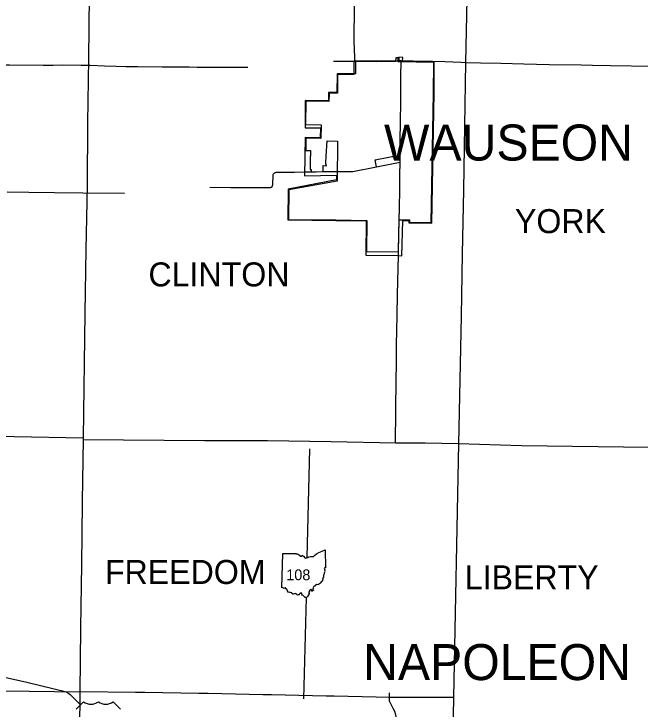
# Model space of a CAD drawing. Extents: x -232 to 448, y 619 to 1059.
# Drawn here: x -26 to 27.5, y 848 to 907.4 of the extents above; entities that cross this region are included whole.
import ezdxf

# ---------------------------------------------------------------- set-up
doc = ezdxf.new("R2010")
doc.units = 0
doc.layers.add('Default', color=7, linetype='Continuous')

msp = doc.modelspace()

# ---------------------------------------------------------------- linework, layer by layer
at = {"layer": 'Default'}
for p, q in [((6.915, 903.671), (6.906, 903.352)), ((7.234, 903.661), (6.915, 903.671)), ((7.225, 903.354), (7.234, 903.661)), ((9.867, 900.61), (9.88, 903.222)), ((9.918, 900.609), (9.932, 903.272)), ((3.195, 902.256), (1.628, 902.256)), ((3.064, 902.205), (1.678, 902.205)), ((0.892, 900.667), (0.884, 899.949)), ((1.61, 900.659), (0.892, 900.667)), ((0.942, 900.615), (0.934, 899.897)), ((1.661, 900.607), (0.942, 900.615)), ((-1.082, 899.971), (-1.108, 897.642)), ((0.884, 899.949), (-1.082, 899.971)), ((-1.031, 899.919), (-1.054, 897.926)), ((0.934, 899.897), (-1.031, 899.919)), ((-1.054, 897.926), (0.259, 897.912)), ((0.203, 897.634), (0.189, 896.784)), ((0.259, 897.912), (0.239, 896.731)), ((-1.083, 896.805), (-1.139, 893.55)), ((0.189, 896.784), (-1.083, 896.805)), ((-1.033, 896.753), (-1.051, 895.715)), ((0.239, 896.731), (-1.033, 896.753)), ((0.77, 896.532), (1.663, 896.516)), ((-1.051, 895.715), (-0.631, 895.707)), ((-0.661, 895.236), (-0.665, 894.973)), ((-0.639, 895.235), (-0.661, 895.236)), ((-0.631, 895.707), (-0.639, 895.235)), ((0.435, 893.898), (0.444, 894.41)), ((0.444, 894.41), (0.733, 894.405)), ((-2.553, 892.395), (-2.573, 889.77)), ((-2.502, 892.341), (-2.521, 889.821)), ((-2.521, 889.821), (1.537, 889.79)), ((-2.573, 889.77), (1.537, 889.738)), ((6.933, 889.788), (7.811, 889.769)), ((7.235, 889.73), (7.758, 889.718)), ((7.758, 889.718), (7.754, 889.537)), ((7.754, 889.537), (9.709, 889.494)), ((7.811, 889.769), (7.807, 889.587)), ((7.807, 889.587), (9.659, 889.546)), ((-3.093, 858.337), (-3.011, 861.266)), ((-3.093, 858.337), (-3.011, 861.266)), ((-20.019, 848.612), (-20.653, 847.978)), ((-20.019, 848.612), (-20.653, 847.978)), ((-16.863, 847.978), (-17.498, 848.612)), ((-16.863, 847.978), (-17.498, 848.612))]:
    msp.add_line(p, q, dxfattribs=at)
for points in [[(3.151, 903.346), (3.148, 903.666), (3.093, 905.035), (3.121, 908.098), (3.152, 909.704)], [(-19.544, 908.989), (-19.61, 903.535), (-19.68, 898.075), (-19.726, 892.691), (-19.827, 887.246), (-19.915, 881.799), (-20.047, 871.155)], [(12.707, 908.674), (12.606, 903.231), (12.512, 897.827), (12.419, 892.307), (12.315, 886.882), (12.229, 881.539), (12.009, 870.683)], [(6.845, 903.279), (6.855, 903.627), (6.639, 903.633), (6.629, 903.298)], [(-32.533, 903.124), (-32.335, 903.121), (-30.979, 903.089), (-27.619, 903.037), (-26.341, 903.018), (-23.475, 903.003), (-22.611, 903.008), (-21.845, 903.012), (-20.215, 903.001), (-19.452, 902.999), (-18.229, 902.954), (-17.231, 902.921), (-16.409, 902.889), (-15.389, 902.882), (-13.299, 902.861), (-11.008, 902.845), (-10.315, 902.84), (-7.632, 902.823), (-5.985, 902.826)], [(1.316, 903.343), (2.342, 903.344)], [(2.342, 903.344), (3.151, 903.346)], [(3.071, 903.308), (3.07, 902.941), (3.064, 902.205)], [(6.629, 903.298), (4.981, 903.286), (3.071, 903.308)], [(3.151, 903.346), (3.671, 903.341), (4.018, 903.346)], [(3.215, 903.358), (3.214, 903.277), (3.196, 902.359), (3.194, 902.267), (3.195, 902.256)], [(6.906, 903.352), (4.981, 903.338), (3.215, 903.358)], [(4.018, 903.346), (5.471, 903.367), (6.241, 903.375)], [(6.241, 903.375), (6.457, 903.377)], [(6.457, 903.377), (6.891, 903.382)], [(9.88, 903.222), (6.845, 903.279)], [(6.891, 903.382), (7.108, 903.384)], [(7.034, 897.926), (7.064, 900.079), (7.088, 902.002), (7.108, 903.384)], [(7.108, 903.384), (7.762, 903.376)], [(9.932, 903.272), (7.225, 903.354)], [(7.762, 903.376), (9.79, 903.35), (10.82, 903.311), (12.206, 903.243), (12.614, 903.23), (13.877, 903.204), (15.604, 903.168), (17.569, 903.113), (19.746, 903.067), (22.482, 903.016), (23.455, 902.993), (24.977, 902.966), (28.539, 902.922), (33.482, 902.898), (34.329, 902.898), (35.664, 902.87), (36.98, 902.858)], [(1.628, 902.256), (1.61, 900.659)], [(1.678, 902.205), (1.661, 900.607)], [(9.659, 889.546), (9.867, 900.61)], [(9.709, 889.494), (9.918, 900.609)], [(-1.108, 897.642), (0.203, 897.634)], [(7.016, 895.15), (7.017, 895.204), (7.028, 896.77), (7.034, 897.926)], [(0.733, 894.405), (0.677, 894.562), (0.661, 894.647), (0.69, 895.211), (0.77, 896.532)], [(1.663, 896.516), (1.627, 893.089)], [(4.872, 894.902), (6.035, 895.131), (6.296, 895.179), (7.017, 895.204)], [(7.008, 894.717), (7.016, 895.15)], [(-0.665, 894.973), (-0.665, 894.069), (-0.576, 894.069), (-0.576, 893.888)], [(4.937, 894.584), (4.872, 894.902)], [(4.991, 894.319), (4.937, 894.584)], [(4.991, 894.319), (7.008, 894.717)], [(6.983, 892.36), (6.985, 892.472), (6.993, 893.612), (7.008, 894.717)], [(1.658, 893.902), (2.409, 893.905), (2.969, 893.914), (4.991, 894.319)], [(-9.228, 892.576), (-7.451, 892.553), (-4.914, 892.538), (-4.044, 892.537), (-3.99, 892.577), (-3.923, 892.638), (-3.875, 892.709), (-3.858, 892.761), (-3.841, 893.662), (-3.81, 893.709), (-3.739, 893.776), (-3.671, 893.818), (-3.565, 893.86), (-2.02, 893.852), (-1.129, 893.881)], [(-1.139, 893.55), (1.576, 893.609)], [(-1.129, 893.881), (-1.065, 893.883), (-0.594, 893.887)], [(-0.594, 893.887), (-0.166, 893.892)], [(-0.576, 893.888), (0.435, 893.898)], [(-0.166, 893.892), (0.434, 893.898), (1.282, 893.901)], [(1.282, 893.901), (1.658, 893.902)], [(1.576, 893.609), (1.577, 893.205)], [(1.577, 893.205), (-2.553, 892.395)], [(1.627, 893.089), (-2.502, 892.341)], [(6.932, 889.786), (6.954, 890.784), (6.983, 892.36)], [(-26.556, 892.164), (-24.693, 892.155), (-22.517, 892.128), (-20.083, 892.102), (-16.53, 892.06)], [(1.537, 889.79), (4.169, 889.737), (4.147, 887.078)], [(1.537, 889.738), (4.117, 889.687)], [(4.117, 889.687), (4.093, 886.767)], [(6.879, 887.052), (6.933, 889.788)], [(6.88, 887.105), (6.907, 888.568), (6.932, 889.786)], [(7.172, 886.697), (7.235, 889.73)], [(4.147, 887.078), (6.879, 887.052)], [(6.873, 886.725), (6.879, 887.052), (6.88, 887.105)], [(4.093, 886.767), (6.865, 886.735), (7.172, 886.697)], [(6.711, 878.803), (6.714, 879.078), (6.761, 881.607), (6.802, 883.396), (6.873, 886.725)], [(6.605, 870.727), (6.683, 876.157), (6.697, 877.402), (6.711, 878.803)], [(-51.822, 871.726), (-47.172, 871.662), (-36.289, 871.455), (-25.953, 871.278), (-20.047, 871.155)], [(-20.049, 871.021), (-20.136, 865.736), (-20.132, 865.618), (-20.19, 860.307), (-20.276, 854.934), (-20.276, 854.856), (-20.351, 849.462)], [(-20.047, 871.155), (-20.049, 871.021)], [(-20.049, 871.021), (-9.681, 870.919), (-4.322, 870.941), (1.111, 870.833), (6.605, 870.727), (9.162, 870.73), (12.009, 870.683)], [(-0.914, 860.93), (-0.697, 870.21)], [(12.009, 870.683), (11.584, 848.966)], [(12.009, 870.683), (17.39, 870.505), (28.277, 870.352), (31.008, 870.398), (33.658, 870.515), (35.764, 870.39), (39.083, 870.359), (41.837, 870.337), (44.377, 870.247), (44.577, 870.248)], [(-3.011, 861.266), (-1.875, 861.285), (-1.892, 861.25), (-1.785, 861.242), (-1.671, 861.18), (-1.575, 861.14), (-1.457, 861.047), (-1.387, 861.048), (-1.357, 861.125), (-1.303, 861.066), (-1.239, 861.055), (-1.128, 860.915), (-1.036, 860.885), (-0.927, 860.933), (-0.845, 860.94), (-0.785, 860.988), (-0.629, 861.029), (-0.586, 861.004), (-0.503, 861.009), (-0.462, 861.027), (-0.39, 861.011), (-0.263, 861.118), (-0.132, 861.243), (0.068, 861.362), (0.368, 861.474), (0.605, 861.574), (0.639, 860.054)], [(-3.011, 861.266), (-1.875, 861.285), (-1.892, 861.25), (-1.785, 861.242), (-1.671, 861.18), (-1.575, 861.14), (-1.457, 861.047), (-1.387, 861.048), (-1.357, 861.125), (-1.303, 861.066), (-1.239, 861.055), (-1.128, 860.915), (-1.036, 860.885), (-0.927, 860.933), (-0.845, 860.94), (-0.785, 860.988), (-0.629, 861.029), (-0.586, 861.004), (-0.503, 861.009), (-0.462, 861.027), (-0.39, 861.011), (-0.263, 861.118), (-0.132, 861.243), (0.068, 861.362), (0.368, 861.474), (0.605, 861.574), (0.639, 860.054)], [(0.639, 860.054), (0.604, 860.033), (0.55, 860.043), (0.513, 860), (0.559, 859.929), (0.58, 859.854), (0.561, 859.771), (0.58, 859.703), (0.567, 859.646), (0.533, 859.589), (0.521, 859.535), (0.492, 859.478), (0.494, 859.446), (0.467, 859.42), (0.472, 859.325), (0.458, 859.272), (0.462, 859.227), (0.417, 859.215), (0.428, 859.178), (0.399, 859.149), (0.405, 859.099), (0.373, 859.067), (0.404, 859.003), (0.379, 858.983), (0.358, 858.905), (0.3, 858.89), (0.185, 858.748), (0.144, 858.694), (0.098, 858.681), (0.073, 858.626), (0.016, 858.625), (-0.069, 858.587), (-0.124, 858.653), (-0.221, 858.574), (-0.232, 858.483), (-0.354, 858.485), (-0.349, 858.439), (-0.377, 858.426), (-0.402, 858.38), (-0.387, 858.297), (-0.444, 858.276), (-0.437, 858.229), (-0.401, 858.2), (-0.384, 858.108), (-0.445, 858.127), (-0.495, 858.05), (-0.546, 858.068), (-0.53, 858.133), (-0.616, 858.211), (-0.698, 858.149), (-0.741, 858.048), (-0.741, 857.981), (-0.802, 857.94), (-0.763, 857.845), (-0.77, 857.779), (-0.769, 857.717), (-0.845, 857.719), (-0.892, 857.551)], [(0.639, 860.054), (0.604, 860.033), (0.55, 860.043), (0.513, 860), (0.559, 859.929), (0.58, 859.854), (0.561, 859.771), (0.58, 859.703), (0.567, 859.646), (0.533, 859.589), (0.521, 859.535), (0.492, 859.478), (0.494, 859.446), (0.467, 859.42), (0.472, 859.325), (0.458, 859.272), (0.462, 859.227), (0.417, 859.215), (0.428, 859.178), (0.399, 859.149), (0.405, 859.099), (0.373, 859.067), (0.404, 859.003), (0.379, 858.983), (0.358, 858.905), (0.3, 858.89), (0.185, 858.748), (0.144, 858.694), (0.098, 858.681), (0.073, 858.626), (0.016, 858.625), (-0.069, 858.587), (-0.124, 858.653), (-0.221, 858.574), (-0.232, 858.483), (-0.354, 858.485), (-0.349, 858.439), (-0.377, 858.426), (-0.402, 858.38), (-0.387, 858.297), (-0.444, 858.276), (-0.437, 858.229), (-0.401, 858.2), (-0.384, 858.108), (-0.445, 858.127), (-0.495, 858.05), (-0.546, 858.068), (-0.53, 858.133), (-0.616, 858.211), (-0.698, 858.149), (-0.741, 858.048), (-0.741, 857.981), (-0.802, 857.94), (-0.763, 857.845), (-0.77, 857.779), (-0.769, 857.717), (-0.845, 857.719), (-0.892, 857.551)], [(-0.892, 857.551), (-1.024, 857.519), (-1.116, 857.5), (-1.149, 857.576), (-1.215, 857.616), (-1.257, 857.693), (-1.352, 857.704), (-1.374, 857.809), (-1.385, 857.895), (-1.514, 857.874), (-1.55, 857.822), (-1.595, 857.808), (-1.622, 857.755), (-1.685, 857.75), (-1.752, 857.725), (-1.796, 857.777), (-1.905, 857.829), (-1.955, 857.856), (-2.058, 857.814), (-2.08, 857.765), (-2.162, 857.787), (-2.182, 857.842), (-2.231, 857.858), (-2.242, 857.917), (-2.349, 857.948), (-2.43, 857.935), (-2.573, 857.982), (-2.582, 858.059), (-2.631, 858.153), (-2.657, 858.218), (-2.747, 858.267), (-2.766, 858.344), (-2.795, 858.342), (-2.821, 858.311), (-2.922, 858.296), (-2.962, 858.328), (-3.018, 858.382), (-3.093, 858.337)], [(-0.892, 857.551), (-1.024, 857.519), (-1.116, 857.5), (-1.149, 857.576), (-1.215, 857.616), (-1.257, 857.693), (-1.352, 857.704), (-1.374, 857.809), (-1.385, 857.895), (-1.514, 857.874), (-1.55, 857.822), (-1.595, 857.808), (-1.622, 857.755), (-1.685, 857.75), (-1.752, 857.725), (-1.796, 857.777), (-1.905, 857.829), (-1.955, 857.856), (-2.058, 857.814), (-2.08, 857.765), (-2.162, 857.787), (-2.182, 857.842), (-2.231, 857.858), (-2.242, 857.917), (-2.349, 857.948), (-2.43, 857.935), (-2.573, 857.982), (-2.582, 858.059), (-2.631, 858.153), (-2.657, 858.218), (-2.747, 858.267), (-2.766, 858.344), (-2.795, 858.342), (-2.821, 858.311), (-2.922, 858.296), (-2.962, 858.328), (-3.018, 858.382), (-3.093, 858.337)], [(-1.197, 848.863), (-0.994, 857.526)], [(-34.288, 852.531), (-29.472, 851.316), (-24.861, 850.267), (-21.469, 849.465), (-21.169, 849.233), (-20.275, 848.355)], [(-52.202, 850.044), (-47.466, 849.91), (-42.069, 849.794), (-36.596, 849.701), (-31.17, 849.597), (-20.351, 849.462)], [(-20.351, 849.462), (-20.52, 829.745), (-20.701, 816.815)], [(11.584, 848.966), (6.838, 848.964), (6.153, 848.981), (1.386, 849.073), (0.706, 849.088), (-3.961, 849.197), (-4.715, 849.208), (-9.369, 849.306), (-10.186, 849.32), (-14.789, 849.383), (-15.578, 849.392), (-20.351, 849.462)], [(6.722, 846.218), (6.743, 847.105), (6.577, 847.703), (6.416, 848.037), (6.119, 848.659), (6.104, 849.38)], [(11.584, 848.966), (11.309, 834.932)]]:
    msp.add_lwpolyline(points, dxfattribs=at)
for centre in [(-19.388, 849.413), (-19.388, 849.413), (-18.128, 849.413), (-18.128, 849.413)]:
    msp.add_arc(centre, 1.019, 231.81301, 308.18697, dxfattribs=at)

# ---------------------------------------------------------------- texts
for s, height, p in [('WAUSEON', 3.078, (5.634, 894.847)), ('YORK', 2.052, (16.819, 888.644)), ('CLINTON', 2.052, (-14.48, 884.093)), ('FREEDOM', 2.052, (-18.199, 858.667)), ('LIBERTY', 2.052, (12.532, 858.213)), ('108', 0.9234, (-2.712, 858.99)), ('NAPOLEON', 3.078, (3.856, 850.455))]:
    msp.add_text(s, height=height, dxfattribs=at).set_placement(p)

doc.saveas('drawing.dxf')
